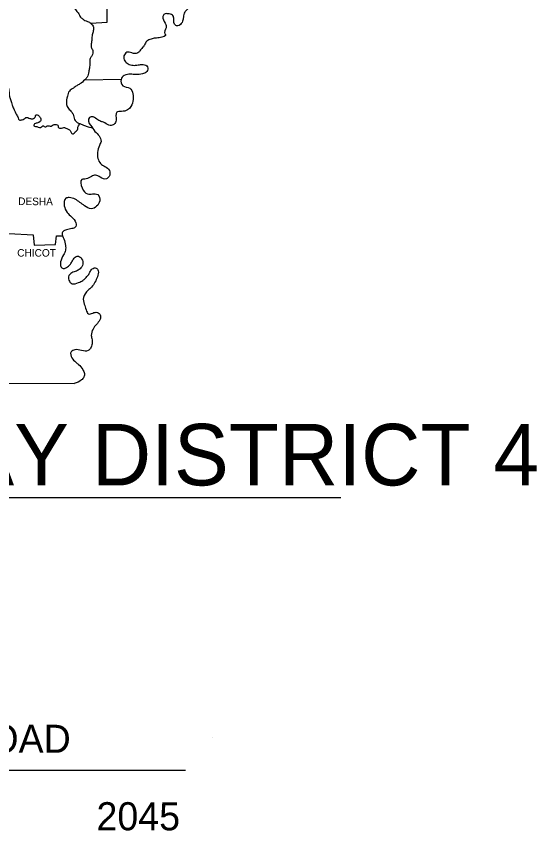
# Model space of a CAD drawing. Extents: x 535214 to 694517, y 381272 to 484355.
# Drawn here: x 679692 to 694517, y 432752 to 455929 of the extents above; entities that cross this region are included whole.
import ezdxf

# ---------------------------------------------------------------- set-up
doc = ezdxf.new("R2010")
doc.units = 0
for name, color, linetype in [('1', 7, 'Continuous'), ('2', 7, 'Continuous'), ('Default', 7, 'Continuous')]:
    doc.layers.add(name, color=color, linetype=linetype)

msp = doc.modelspace()

# ---------------------------------------------------------------- linework, layer by layer
at = {"layer": '1'}
for p, q in [((655872, 442234), (688934, 442234)), ((685279, 435399), (685279, 435399)), ((660875, 434480), (684515, 434480))]:
    msp.add_line(p, q, dxfattribs=at)
for points in [[(681499, 452874), (681611, 452830), (681740, 452786), (681862, 452754)], [(663009, 449554), (663019, 445509), (681344, 445479)]]:
    msp.add_lwpolyline(points, dxfattribs=at)
for points in [[(685554, 458984), (685439, 458839), (685269, 458929), (685269, 459049), (685294, 459174), (685234, 459254), (685129, 459219), (685129, 459064), (685119, 458914), (685089, 458699), (685159, 458634), (685319, 458614), (685434, 458584), (685504, 458469), (685499, 458329), (685444, 458194), (685364, 458084), (685239, 458044), (685139, 458109), (685099, 458239), (685054, 458354), (684969, 458439), (684879, 458344), (684859, 458169), (684864, 458019), (684864, 457814), (684994, 457679), (685074, 457524), (685049, 457384), (684954, 457219), (684914, 457074), (684874, 456879), (684879, 456664), (684844, 456454), (684774, 456314), (684644, 456199), (684559, 456124), (684489, 456049), (684454, 455899), (684429, 455794), (684334, 455669), (684259, 455659), (684199, 455709), (684179, 455794), (684179, 455879), (684139, 455964), (684014, 455999), (683914, 455994), (683869, 455924), (683934, 455729), (683959, 455604), (683924, 455434), (683944, 455414), (683764, 455319), (683619, 455304), (683499, 455269), (683384, 455194), (683329, 455084), (683249, 454994), (683179, 454909), (683084, 454869), (682979, 454889), (682839, 454904), (682759, 454804), (682784, 454659), (682879, 454574), (683019, 454534), (683164, 454544), (683304, 454559), (683434, 454489), (683409, 454354), (683284, 454289), (683099, 454269), (682949, 454284), (682769, 454244), (682679, 454129), (682729, 453954), (682924, 453884), (683014, 453719), (683019, 453564), (682954, 453359), (682864, 453264), (682689, 453224), (682554, 453199), (682534, 452969), (682474, 452854), (682369, 452819), (682219, 452894), (682129, 452929), (682019, 452979), (681879, 453064), (681774, 453049), (681804, 452829), (681814, 452819), (681934, 452654), (682054, 452524), (682109, 452369)], [(680374, 457374), (680389, 457169), (680509, 457139), (680559, 457084), (680584, 456969), (680669, 456919), (680784, 456849), (680854, 456799), (680904, 456719), (680934, 456589), (681014, 456504), (681124, 456464), (681204, 456369), (681254, 456234), (681334, 456174), (681414, 456069), (681454, 456024), (681524, 455904), (681594, 455844), (681644, 455809), (681724, 455784), (681824, 455719), (681889, 455619), (681889, 455544), (681864, 455429), (681844, 455309), (681834, 455174), (681824, 455054), (681869, 454954), (681844, 454804), (681794, 454724), (681789, 454614), (681774, 454449), (681754, 454354), (681709, 454199), (681644, 454119)], [(681644, 454119), (681504, 454004), (681414, 453954), (681319, 453884), (681204, 453799), (681149, 453654), (681119, 453454), (681159, 453334), (681249, 453229), (681309, 453144), (681354, 452994), (681464, 452889), (681499, 452874)], [(682109, 452369), (682059, 452254), (682004, 452054), (682019, 451884), (682094, 451739), (682214, 451659), (682344, 451544), (682334, 451369), (682259, 451304), (682084, 451349), (681949, 451409), (681834, 451374), (681679, 451299), (681564, 451284), (681569, 451044), (681724, 450874), (681859, 450874), (682014, 450854), (682069, 450674), (681979, 450524), (681829, 450449), (681639, 450539), (681504, 450634), (681369, 450724), (681199, 450769), (681104, 450749), (681059, 450539), (681139, 450349), (681269, 450219), (681389, 450049), (681369, 449924), (681279, 449889), (681119, 449854), (681024, 449804), (680999, 449764), (681049, 449594), (681094, 449409), (681094, 449269), (681039, 449139), (680954, 448939), (680964, 448809), (681024, 448749), (681099, 448769), (681199, 448839), (681264, 448919), (681319, 449019), (681424, 449104), (681554, 449029), (681584, 448874), (681509, 448739), (681404, 448679), (681274, 448629), (681179, 448519), (681204, 448389), (681279, 448319), (681464, 448354), (681589, 448409), (681659, 448479), (681744, 448564), (681789, 448649), (681854, 448739), (681969, 448764), (682024, 448689), (682004, 448519), (681934, 448359), (681839, 448224), (681734, 448129), (681604, 447924), (681629, 447734), (681679, 447579), (681749, 447459), (681869, 447484), (682004, 447499), (682084, 447434), (682074, 447294), (681974, 447159), (681879, 447029), (681829, 446849), (681849, 446724), (681849, 446609), (681809, 446484), (681739, 446414), (681554, 446419), (681359, 446439), (681254, 446379), (681274, 446209), (681389, 446084), (681469, 446019), (681584, 445879), (681634, 445764), (681619, 445664), (681549, 445579), (681344, 445479)]]:
    msp.add_spline(points, degree=3, dxfattribs=at)
at = {"layer": 'Default'}
msp.add_line((681644, 454120), (682682, 454135), dxfattribs=at)
for points in [[(681813, 455729), (682279, 455759), (682274, 456774), (681909, 456799), (681929, 458784), (681614, 458829), (681604, 460164), (685894, 460194)], [(679479, 449751), (680174, 449709), (680204, 449419), (680809, 449439), (680834, 449684), (681021, 449684)]]:
    msp.add_lwpolyline(points, dxfattribs=at)
msp.add_spline([(678474, 454789), (678549, 454739), (678654, 454744), (678724, 454774), (678779, 454769), (678854, 454724), (678904, 454664), (678939, 454619), (678964, 454549), (678964, 454484), (678989, 454394), (679019, 454359), (679059, 454294), (679084, 454234), (679099, 454194), (679154, 454129), (679204, 454134), (679249, 454129), (679309, 454094), (679399, 454024), (679414, 454004), (679474, 453874), (679484, 453794), (679494, 453689), (679514, 453589), (679554, 453479), (679574, 453404), (679619, 453299), (679649, 453229), (679689, 453139), (679749, 453039), (679774, 452979), (679859, 452984), (679919, 453009), (679964, 453049), (680019, 453044), (680079, 453024), (680159, 453009), (680209, 453039), (680234, 453059), (680239, 453104), (680284, 453129), (680334, 453094), (680389, 453014), (680389, 452964), (680369, 452934), (680304, 452894), (680214, 452864), (680189, 452829), (680274, 452789), (680409, 452779), (680444, 452809), (680534, 452784), (680569, 452809), (680689, 452804), (680744, 452844), (680854, 452839), (680889, 452814), (680889, 452769), (680979, 452749), (681044, 452764), (681129, 452739), (681204, 452699), (681244, 452644), (681294, 452584), (681339, 452599), (681374, 452644), (681449, 452724), (681449, 452774), (681469, 452809), (681499, 452874)], degree=3, dxfattribs=at)

# ---------------------------------------------------------------- texts
at = {"layer": '1'}
msp.add_text('DESIGN TRAFFIC DATA ACCESS ROAD', height=800, dxfattribs=at).set_placement((661094, 434969))
at = {"layer": '2'}
for s, height, p in [('ARKANSAS HIGHWAY DISTRICT 4', 1750, (656617, 442579)), ('2045', 800, (681977, 432764))]:
    msp.add_text(s, height=height, dxfattribs=at).set_placement(p)
at = {"layer": 'Default'}
msp.add_text('DESHA', height=215, rotation=359.3704, dxfattribs=at).set_placement((679744, 450559))
msp.add_text('CHICOT', height=215, dxfattribs=at).set_placement((679719, 449089))

doc.saveas('drawing.dxf')
